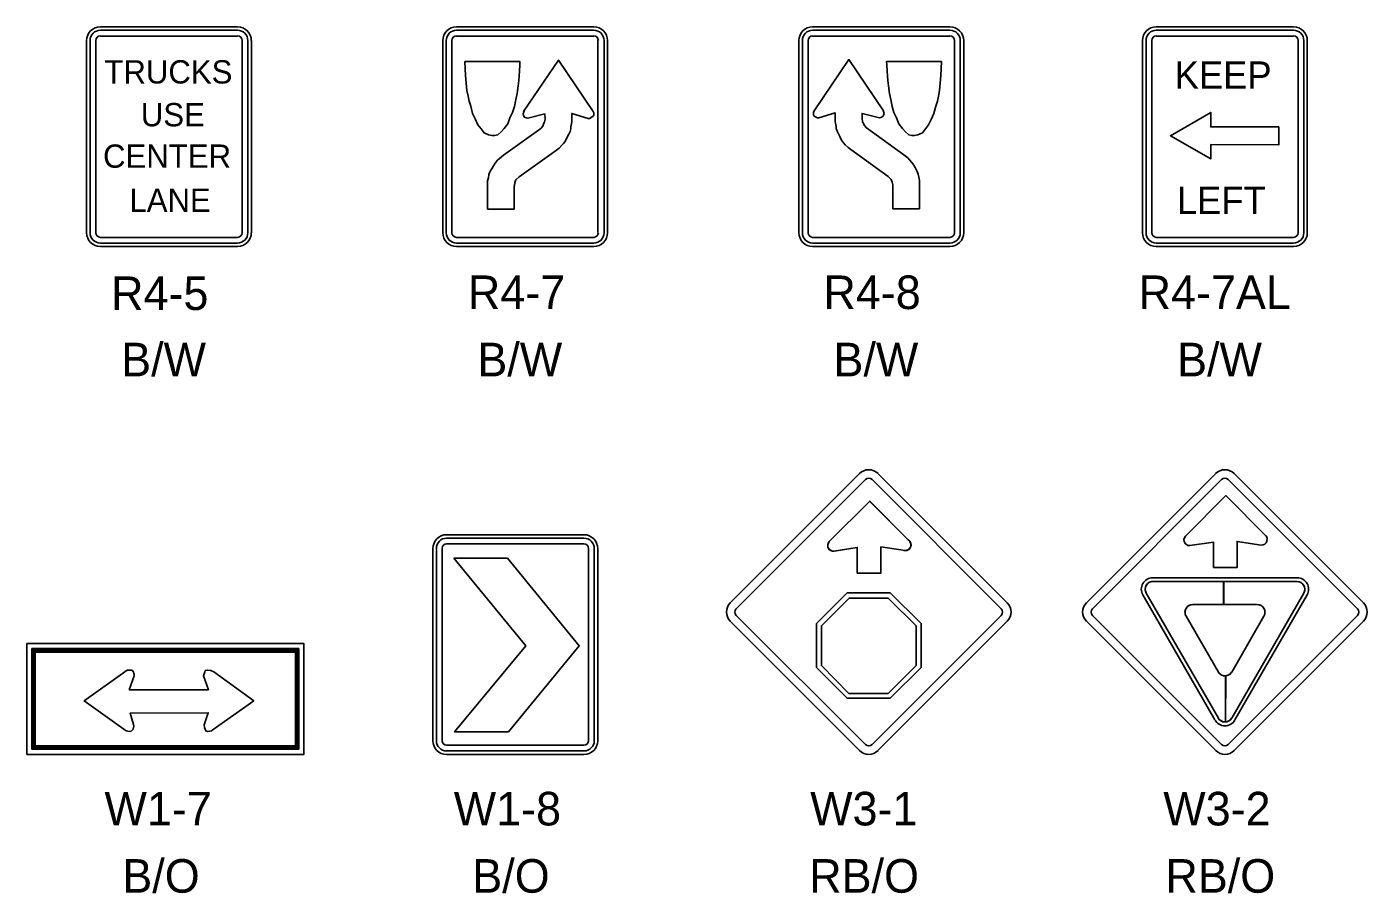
# Model space of a CAD drawing. Extents: x 10000 to 10794, y 10000 to 10499.
# Drawn here: x 10653.6 to 10793.3, y 10408.8 to 10499 of the extents above; entities that cross this region are included whole.
import ezdxf

# ---------------------------------------------------------------- set-up
doc = ezdxf.new("R2010")
doc.units = 0
doc.layers.add('DSIndex', color=7, linetype='Continuous')

msp = doc.modelspace()

# ---------------------------------------------------------------- linework, layer by layer
at = {"layer": 'DSIndex'}
for p, q in [((10661.29, 10499.04), (10675.59, 10499.04)), ((10661.29, 10498.68), (10675.59, 10498.68)), ((10698.41, 10499.04), (10712.71, 10499.04)), ((10698.41, 10498.68), (10712.71, 10498.68)), ((10749.83, 10499.04), (10735.52, 10499.04)), ((10749.83, 10498.68), (10735.52, 10498.68)), ((10771.33, 10499.04), (10785.64, 10499.04)), ((10771.33, 10498.68), (10785.64, 10498.68)), ((10659.86, 10477.58), (10659.86, 10497.61)), ((10659.86, 10477.58), (10659.86, 10497.61)), ((10660.22, 10477.58), (10660.22, 10497.61)), ((10660.81, 10477.58), (10660.81, 10497.61)), ((10661.29, 10498.08), (10675.59, 10498.08)), ((10676.07, 10477.58), (10676.07, 10497.61)), ((10676.67, 10477.58), (10676.67, 10497.61)), ((10677.03, 10477.58), (10677.03, 10497.61)), ((10696.98, 10477.58), (10696.98, 10497.61)), ((10696.98, 10477.58), (10696.98, 10497.61)), ((10697.33, 10477.58), (10697.33, 10497.61)), ((10697.93, 10477.58), (10697.93, 10497.61)), ((10698.41, 10498.08), (10712.71, 10498.08)), ((10713.15, 10477.6), (10713.15, 10497.63)), ((10713.78, 10477.58), (10713.78, 10497.61)), ((10714.14, 10477.58), (10714.14, 10497.61)), ((10734.09, 10477.58), (10734.09, 10497.61)), ((10734.09, 10477.58), (10734.09, 10497.61)), ((10734.45, 10477.58), (10734.45, 10497.61)), ((10735.05, 10477.58), (10735.05, 10497.61)), ((10749.83, 10498.08), (10735.52, 10498.08)), ((10750.3, 10477.58), (10750.3, 10497.61)), ((10750.9, 10477.58), (10750.9, 10497.61)), ((10751.26, 10477.58), (10751.26, 10497.61)), ((10769.9, 10477.58), (10769.9, 10497.61)), ((10769.9, 10477.58), (10769.9, 10497.61)), ((10770.26, 10477.58), (10770.26, 10497.61)), ((10770.86, 10477.58), (10770.86, 10497.61)), ((10771.33, 10498.08), (10785.64, 10498.08)), ((10786.12, 10477.58), (10786.12, 10497.61)), ((10786.71, 10477.58), (10786.71, 10497.61)), ((10787.07, 10477.58), (10787.07, 10497.61)), ((10661.29, 10477.1), (10675.59, 10477.1)), ((10661.29, 10476.51), (10675.59, 10476.51)), ((10698.41, 10477.1), (10712.71, 10477.1)), ((10698.41, 10476.51), (10712.71, 10476.51)), ((10749.83, 10477.1), (10735.52, 10477.1)), ((10749.83, 10476.51), (10735.52, 10476.51)), ((10771.33, 10477.1), (10785.64, 10477.1)), ((10771.33, 10476.51), (10785.64, 10476.51)), ((10661.29, 10476.15), (10675.59, 10476.15)), ((10698.41, 10476.15), (10712.71, 10476.15)), ((10749.83, 10476.15), (10735.52, 10476.15)), ((10771.33, 10476.15), (10785.64, 10476.15)), ((10726.94, 10439.02), (10740.41, 10452.49)), ((10727.56, 10438.41), (10741.02, 10451.86)), ((10741.72, 10451.86), (10755.17, 10438.41)), ((10742.33, 10452.49), (10755.8, 10439.02)), ((10764.05, 10439.02), (10777.53, 10452.49)), ((10764.68, 10438.41), (10778.14, 10451.86)), ((10778.83, 10451.86), (10792.29, 10438.41)), ((10779.44, 10452.49), (10792.92, 10439.02)), ((10741.47, 10449.62), (10737.25, 10445.41)), ((10741.46, 10449.61), (10745.62, 10445.44)), ((10697.38, 10446.12), (10711.69, 10446.12)), ((10697.38, 10445.76), (10711.69, 10445.76)), ((10695.95, 10424.66), (10695.95, 10444.69)), ((10696.31, 10424.66), (10696.31, 10444.69)), ((10696.91, 10424.66), (10696.91, 10444.69)), ((10697.38, 10445.17), (10711.69, 10445.17)), ((10712.16, 10424.66), (10712.16, 10444.69)), ((10712.76, 10424.66), (10712.76, 10444.69)), ((10713.12, 10424.66), (10713.12, 10444.69)), ((10740.16, 10444.79), (10737.76, 10444.42)), ((10740.16, 10442.13), (10740.16, 10444.79)), ((10742.64, 10442.13), (10742.64, 10444.85)), ((10742.64, 10444.85), (10745.15, 10444.46)), ((10740.16, 10442.13), (10742.64, 10442.13)), ((10770.97, 10441.64), (10786.02, 10441.64)), ((10735.92, 10436.87), (10739.12, 10440.08)), ((10739.12, 10440.08), (10743.61, 10440.08)), ((10746.82, 10436.87), (10743.61, 10440.08)), ((10777.8, 10427.01), (10770.28, 10440.04)), ((10770.97, 10441.24), (10786.02, 10441.24)), ((10786.71, 10440.04), (10779.19, 10427.01)), ((10777.45, 10426.82), (10769.93, 10439.84)), ((10775.13, 10438.84), (10781.86, 10438.84)), ((10787.05, 10439.84), (10779.53, 10426.82)), ((10741.02, 10424.25), (10727.56, 10437.71)), ((10755.17, 10437.71), (10741.72, 10424.25)), ((10778.14, 10424.25), (10764.68, 10437.71)), ((10777.8, 10431.81), (10774.44, 10437.64)), ((10792.29, 10437.71), (10778.83, 10424.25)), ((10782.55, 10437.64), (10779.19, 10431.81)), ((10740.41, 10423.63), (10726.94, 10437.1)), ((10735.92, 10432.29), (10735.92, 10436.87)), ((10735.92, 10436.87), (10735.92, 10436.87)), ((10755.8, 10437.1), (10742.33, 10423.63)), ((10746.82, 10432.3), (10746.82, 10436.87)), ((10746.82, 10436.87), (10746.82, 10436.87)), ((10777.53, 10423.63), (10764.05, 10437.1)), ((10792.92, 10437.1), (10779.44, 10423.63)), ((10705.6, 10434.56), (10705.6, 10434.56)), ((10711.17, 10434.57), (10711.17, 10434.57)), ((10654.33, 10423.93), (10654.33, 10434.08)), ((10739.13, 10429.08), (10735.92, 10432.3)), ((10743.6, 10429.08), (10746.82, 10432.3)), ((10739.07, 10429.08), (10739.11, 10429.08)), ((10743.6, 10429.08), (10739.13, 10429.08)), ((10697.38, 10424.18), (10711.69, 10424.18)), ((10697.38, 10423.59), (10711.69, 10423.59)), ((10697.38, 10423.23), (10711.69, 10423.23))]:
    msp.add_line(p, q, dxfattribs=at)
for points in [[(10699.29, 10495.44), (10705, 10495.44), (10704.99, 10495.08), (10704.96, 10494.42), (10704.89, 10493.44), (10704.82, 10492.89), (10704.72, 10492.1), (10704.58, 10491.45), (10704.44, 10490.73), (10704.25, 10490.11), (10703.98, 10489.54), (10703.74, 10488.94), (10703.36, 10488.43), (10703.08, 10488.12), (10702.7, 10487.79), (10702.38, 10487.7), (10702.1, 10487.7), (10701.74, 10487.77), (10701.28, 10487.98), (10700.97, 10488.41), (10700.63, 10488.82), (10700.37, 10489.39), (10700.08, 10490.02), (10699.89, 10490.76), (10699.72, 10491.3), (10699.61, 10491.81), (10699.49, 10492.4), (10699.42, 10493.17), (10699.36, 10493.96)], [(10701.64, 10480.04), (10701.64, 10482.42), (10701.64, 10482.66), (10701.64, 10482.99), (10701.73, 10483.32), (10701.78, 10483.65), (10701.92, 10483.99), (10702.11, 10484.32), (10702.25, 10484.56), (10702.44, 10484.84), (10702.68, 10485.13), (10702.87, 10485.32), (10703.3, 10485.66), (10707.19, 10488.46), (10707.39, 10488.69), (10707.48, 10488.88), (10707.58, 10489.12), (10707.63, 10489.4), (10707.62, 10489.97), (10705.84, 10489.51), (10705.68, 10489.55), (10705.49, 10489.64), (10705.39, 10489.79), (10705.34, 10489.97), (10705.44, 10490.26), (10705.4, 10490.22), (10709.02, 10495.57), (10712.64, 10490.22), (10712.71, 10490.07), (10712.71, 10489.83), (10712.61, 10489.69), (10712.42, 10489.59), (10712.33, 10489.5), (10712.14, 10489.5), (10710.42, 10490.01), (10710.42, 10489.4), (10710.43, 10489.12), (10710.33, 10488.6), (10710.33, 10488.41), (10710.24, 10488.12), (10710.1, 10487.84), (10709.95, 10487.55), (10709.76, 10487.17), (10709.57, 10486.89), (10709.38, 10486.7), (10709.1, 10486.41), (10708.81, 10486.2), (10704.93, 10483.4), (10704.58, 10483.08), (10704.49, 10482.8), (10704.44, 10482.51), (10704.43, 10482.42), (10704.43, 10480.04)], [(10746.66, 10480.09), (10746.66, 10482.47), (10746.67, 10482.71), (10746.67, 10483.04), (10746.57, 10483.37), (10746.53, 10483.7), (10746.38, 10484.04), (10746.19, 10484.37), (10746.05, 10484.61), (10745.86, 10484.89), (10745.62, 10485.18), (10745.43, 10485.37), (10745.01, 10485.71), (10741.12, 10488.51), (10740.92, 10488.74), (10740.82, 10488.93), (10740.73, 10489.17), (10740.67, 10489.45), (10740.68, 10490.02), (10742.47, 10489.56), (10742.63, 10489.6), (10742.82, 10489.69), (10742.91, 10489.83), (10742.96, 10490.02), (10742.87, 10490.31), (10742.9, 10490.27), (10739.28, 10495.62), (10735.67, 10490.27), (10735.6, 10490.12), (10735.6, 10489.88), (10735.69, 10489.74), (10735.88, 10489.64), (10735.98, 10489.55), (10736.17, 10489.55), (10737.88, 10490.06), (10737.88, 10489.45), (10737.88, 10489.17), (10737.97, 10488.65), (10737.97, 10488.46), (10738.07, 10488.17), (10738.21, 10487.89), (10738.35, 10487.6), (10738.54, 10487.22), (10738.73, 10486.94), (10738.92, 10486.75), (10739.21, 10486.46), (10739.49, 10486.25), (10743.38, 10483.45), (10743.72, 10483.13), (10743.82, 10482.85), (10743.86, 10482.56), (10743.88, 10482.47), (10743.88, 10480.09)], [(10748.94, 10495.44), (10743.23, 10495.44), (10743.25, 10495.08), (10743.28, 10494.42), (10743.35, 10493.44), (10743.42, 10492.89), (10743.52, 10492.1), (10743.66, 10491.45), (10743.79, 10490.73), (10743.98, 10490.11), (10744.26, 10489.54), (10744.5, 10488.94), (10744.88, 10488.43), (10745.15, 10488.12), (10745.53, 10487.79), (10745.86, 10487.7), (10746.13, 10487.7), (10746.49, 10487.77), (10746.96, 10487.98), (10747.27, 10488.41), (10747.61, 10488.82), (10747.87, 10489.39), (10748.16, 10490.02), (10748.35, 10490.76), (10748.52, 10491.3), (10748.62, 10491.81), (10748.74, 10492.4), (10748.81, 10493.17), (10748.88, 10493.96)], [(10784.11, 10488.63), (10784.11, 10486.75), (10777.01, 10486.77), (10777.01, 10485.27), (10772.81, 10487.69), (10777.01, 10490.11), (10777.01, 10488.61)], [(10777.28, 10442.7), (10779.75, 10442.7), (10779.75, 10445.42), (10782.26, 10445.04), (10782.47, 10445.07), (10782.66, 10445.15), (10782.78, 10445.29), (10782.86, 10445.46), (10782.87, 10445.75), (10782.78, 10445.99), (10782.74, 10446.02), (10778.58, 10450.2), (10774.37, 10445.98), (10774.21, 10445.67), (10774.23, 10445.41), (10774.36, 10445.17), (10774.61, 10445.01), (10774.84, 10444.98), (10777.28, 10445.36)], [(10740.16, 10442.13), (10742.64, 10442.13), (10742.64, 10444.85), (10745.15, 10444.46), (10745.35, 10444.49), (10745.55, 10444.58), (10745.66, 10444.72), (10745.75, 10444.89), (10745.76, 10445.17), (10745.66, 10445.41), (10745.62, 10445.44), (10741.47, 10449.62), (10737.25, 10445.41), (10737.1, 10445.1), (10737.12, 10444.83), (10737.24, 10444.6), (10737.5, 10444.44), (10737.72, 10444.41), (10740.16, 10444.79)], [(10698.13, 10443.69), (10703.72, 10443.69), (10711.19, 10434.55), (10703.81, 10425.57), (10698.2, 10425.57), (10705.62, 10434.54)], [(10778.35, 10441.24), (10778.35, 10438.84), (10775.13, 10438.84), (10774.98, 10438.83), (10774.88, 10438.8), (10774.78, 10438.75), (10774.69, 10438.7), (10774.62, 10438.66), (10774.57, 10438.61), (10774.5, 10438.53), (10774.45, 10438.47), (10774.4, 10438.38), (10774.36, 10438.28), (10774.34, 10438.19), (10774.32, 10438.1), (10774.33, 10438), (10774.34, 10437.86), (10774.38, 10437.74), (10774.44, 10437.64), (10777.8, 10431.81), (10777.86, 10431.71), (10777.94, 10431.64), (10778.02, 10431.58), (10778.1, 10431.53), (10778.17, 10431.48), (10778.25, 10431.45), (10778.35, 10431.43), (10778.42, 10431.42), (10778.49, 10431.42), (10778.55, 10431.42), (10778.54, 10426.62), (10778.4, 10426.62), (10778.3, 10426.63), (10778.23, 10426.65), (10778.13, 10426.68), (10778.06, 10426.75), (10778, 10426.79), (10777.94, 10426.82), (10777.9, 10426.88), (10777.86, 10426.93), (10777.8, 10427.01), (10770.28, 10440.04), (10770.27, 10440.08), (10770.23, 10440.17), (10770.2, 10440.27), (10770.18, 10440.34), (10770.18, 10440.43), (10770.2, 10440.57), (10770.2, 10440.66), (10770.24, 10440.75), (10770.29, 10440.85), (10770.28, 10440.84), (10770.34, 10440.94), (10770.43, 10441.03), (10770.52, 10441.11), (10770.62, 10441.16), (10770.74, 10441.21), (10770.84, 10441.24), (10770.97, 10441.24)], [(10778.38, 10441.24), (10778.38, 10438.84), (10781.86, 10438.84), (10782.05, 10438.82), (10782.2, 10438.77), (10782.28, 10438.72), (10782.4, 10438.63), (10782.52, 10438.49), (10782.6, 10438.35), (10782.65, 10438.19), (10782.66, 10438.02), (10782.65, 10437.88), (10782.6, 10437.73), (10782.55, 10437.64), (10779.19, 10431.81), (10779.1, 10431.7), (10779.03, 10431.6), (10778.92, 10431.54), (10778.81, 10431.47), (10778.69, 10431.44), (10778.57, 10431.42), (10778.54, 10426.62), (10778.66, 10426.62), (10778.75, 10426.66), (10778.83, 10426.69), (10778.9, 10426.74), (10778.96, 10426.77), (10779.03, 10426.82), (10779.09, 10426.88), (10779.15, 10426.95), (10779.19, 10427.01), (10779.19, 10427.01), (10786.71, 10440.04), (10786.74, 10440.1), (10786.79, 10440.22), (10786.8, 10440.32), (10786.82, 10440.42), (10786.82, 10440.52), (10786.79, 10440.64), (10786.77, 10440.72), (10786.74, 10440.79), (10786.7, 10440.87), (10786.64, 10440.95), (10786.57, 10441.01), (10786.51, 10441.07), (10786.43, 10441.13), (10786.33, 10441.18), (10786.24, 10441.21), (10786.15, 10441.22), (10786.02, 10441.24)], [(10739.3, 10429.57), (10743.39, 10429.57), (10746.3, 10432.48), (10746.3, 10436.62), (10743.4, 10439.52), (10739.34, 10439.52), (10736.44, 10436.61), (10736.44, 10432.48)], [(10664.3, 10429.95), (10664.82, 10431.41), (10664.81, 10431.56), (10664.71, 10431.89), (10664.54, 10432.02), (10664.34, 10432.02), (10664.07, 10432.01), (10659.6, 10428.81), (10663.97, 10425.69), (10664.17, 10425.65), (10664.37, 10425.61), (10664.51, 10425.66), (10664.7, 10425.87), (10664.78, 10426.18), (10664.75, 10426.36), (10664.39, 10427.52), (10672.53, 10427.57), (10672.11, 10426.31), (10672.16, 10426.02), (10672.28, 10425.68), (10672.45, 10425.63), (10672.89, 10425.68), (10673.06, 10425.82), (10677.27, 10428.81), (10673.11, 10431.85), (10672.79, 10431.99), (10672.45, 10432.01), (10672.23, 10431.97), (10672.18, 10431.82), (10672.04, 10431.43), (10672.56, 10429.96)]]:
    msp.add_lwpolyline(points, close=True, dxfattribs=at)
for points in [[(10653.63, 10434.78), (10682.5, 10434.78), (10682.5, 10423.23), (10653.63, 10423.23), (10653.63, 10434.78)], [(10654.16, 10434.25), (10681.97, 10434.25), (10681.97, 10423.76), (10654.16, 10423.76), (10654.16, 10434.25)], [(10654.22, 10434.19), (10681.91, 10434.19), (10681.91, 10423.82), (10654.22, 10423.82), (10654.22, 10434.19)], [(10654.27, 10434.13), (10681.85, 10434.13), (10681.85, 10423.88), (10654.27, 10423.88), (10654.27, 10434.13)], [(10654.33, 10434.08), (10681.8, 10434.08), (10681.8, 10423.93), (10654.33, 10423.93)], [(10654.39, 10434.02), (10681.74, 10434.02)], [(10654.39, 10434.02), (10681.74, 10434.02), (10681.74, 10423.99), (10654.39, 10423.99), (10654.39, 10434.02)], [(10654.45, 10433.96), (10681.68, 10433.96), (10681.68, 10424.05), (10654.45, 10424.05), (10654.45, 10433.96)], [(10654.5, 10433.9), (10681.62, 10433.9), (10681.62, 10424.11), (10654.5, 10424.11), (10654.5, 10433.9)]]:
    msp.add_lwpolyline(points, dxfattribs=at)
for centre, radius, start, end in [((10661.29, 10497.61), 1.43, 90, 180), ((10661.29, 10497.61), 1.07, 90, 180), ((10675.59, 10497.61), 1.43, 0, 90), ((10675.59, 10497.61), 1.07, 0, 90), ((10698.41, 10497.61), 1.43, 90, 180), ((10698.41, 10497.61), 1.07, 90, 180), ((10712.71, 10497.61), 1.43, 0, 90), ((10712.71, 10497.61), 1.07, 0, 90), ((10735.52, 10497.61), 1.43, 90, 180), ((10735.52, 10497.61), 1.07, 90, 180), ((10749.83, 10497.61), 1.43, 0, 90), ((10749.83, 10497.61), 1.07, 0, 90), ((10771.33, 10497.61), 1.43, 90, 180), ((10771.33, 10497.61), 1.07, 90, 180), ((10785.64, 10497.61), 1.43, 0, 90), ((10785.64, 10497.61), 1.07, 0, 90), ((10661.29, 10497.61), 0.477, 90, 180), ((10675.59, 10497.61), 0.477, 0, 90), ((10698.41, 10497.61), 0.477, 90, 180), ((10712.71, 10497.61), 0.477, 0, 90), ((10735.52, 10497.61), 0.477, 90, 180), ((10749.83, 10497.61), 0.477, 0, 90), ((10771.33, 10497.61), 0.477, 90, 180), ((10785.64, 10497.61), 0.477, 0, 90), ((10661.29, 10477.58), 1.43, 180, 270), ((10661.29, 10477.58), 1.07, 180, 270), ((10661.29, 10477.58), 0.477, 180, 270), ((10675.59, 10477.58), 1.43, 270, 0), ((10675.59, 10477.58), 1.07, 270, 0), ((10675.59, 10477.58), 0.477, 270, 0), ((10698.41, 10477.58), 1.43, 180, 270), ((10698.41, 10477.58), 1.07, 180, 270), ((10698.41, 10477.58), 0.477, 180, 270), ((10712.71, 10477.58), 1.43, 270, 0), ((10712.71, 10477.58), 1.07, 270, 0), ((10712.71, 10477.58), 0.477, 270, 0), ((10735.52, 10477.58), 1.43, 180, 270), ((10735.52, 10477.58), 1.07, 180, 270), ((10735.52, 10477.58), 0.477, 180, 270), ((10749.83, 10477.58), 1.43, 270, 0), ((10749.83, 10477.58), 1.07, 270, 0), ((10749.83, 10477.58), 0.477, 270, 0), ((10771.33, 10477.58), 1.43, 180, 270), ((10771.33, 10477.58), 1.07, 180, 270), ((10771.33, 10477.58), 0.477, 180, 270), ((10785.64, 10477.58), 1.43, 270, 0), ((10785.64, 10477.58), 1.07, 270, 0), ((10785.64, 10477.58), 0.477, 270, 0), ((10741.37, 10451.53), 1.36, 45, 135), ((10778.48, 10451.53), 1.36, 45, 135), ((10741.37, 10451.52), 0.49, 45, 135), ((10778.48, 10451.52), 0.49, 45, 135), ((10697.38, 10444.69), 1.43, 90, 180), ((10697.38, 10444.69), 1.07, 90, 180), ((10711.69, 10444.69), 1.43, 0, 90), ((10711.69, 10444.69), 1.07, 0, 90), ((10697.38, 10444.69), 0.477, 90, 180), ((10711.69, 10444.69), 0.477, 0, 90), ((10737.68, 10445), 0.591, 135.3904, 277.6306), ((10745.18, 10445.06), 0.591, 255.3843, 60.3263), ((10770.97, 10440.44), 1.2, 90, 210), ((10786.01, 10440.44), 1.2, 330, 90), ((10770.97, 10440.44), 0.8, 90, 210), ((10786.01, 10440.44), 0.8, 330, 90), ((10727.9, 10438.06), 1.36, 135, 225), ((10754.84, 10438.06), 1.36, 315, 45), ((10765.01, 10438.06), 1.36, 135, 225), ((10775.13, 10438.04), 0.8, 90, 210), ((10781.86, 10438.04), 0.8, 330, 90), ((10791.95, 10438.06), 1.36, 315, 45), ((10727.91, 10438.06), 0.49, 135, 225), ((10754.83, 10438.06), 0.49, 315, 45), ((10765.02, 10438.06), 0.49, 135, 225), ((10791.94, 10438.06), 0.49, 315, 45), ((10778.49, 10432.21), 0.8, 210, 330), ((10778.49, 10427.41), 1.2, 210, 330), ((10778.49, 10427.41), 0.8, 210, 330), ((10697.38, 10424.66), 1.43, 180, 270), ((10697.38, 10424.66), 1.07, 180, 270), ((10697.38, 10424.66), 0.477, 180, 270), ((10711.69, 10424.66), 1.43, 270, 0), ((10711.69, 10424.66), 1.07, 270, 0), ((10711.69, 10424.66), 0.477, 270, 0), ((10741.37, 10424.59), 1.36, 225, 315), ((10741.37, 10424.6), 0.49, 225, 315), ((10778.49, 10424.59), 1.36, 225, 315), ((10778.48, 10424.6), 0.49, 225, 315)]:
    msp.add_arc(centre, radius, start, end, dxfattribs=at)

# ---------------------------------------------------------------- texts
for s, height, p in [('TRUCKS', 2.427, (10661.71, 10493.13)), ('KEEP', 2.831, (10773.25, 10492.6)), ('USE', 2.425, (10665.51, 10488.67)), ('CENTER', 2.427, (10661.57, 10484.35)), ('LANE', 2.427, (10664.32, 10479.76)), ('LEFT', 2.831, (10773.48, 10479.54)), ('R4-5', 3.5, (10662.41, 10469.53)), ('R4-7', 3.5, (10699.59, 10469.63)), ('R4-8', 3.5, (10736.64, 10469.63)), ('R4-7AL', 3.5, (10769.49, 10469.63)), ('B/W', 3.5, (10663.46, 10462.62)), ('B/W', 3.5, (10700.58, 10462.62)), ('B/W', 3.5, (10737.69, 10462.62)), ('B/W', 3.5, (10773.5, 10462.62)), ('W1-7', 3.5, (10661.72, 10415.83)), ('W1-8', 3.5, (10698.12, 10415.83)), ('W3-1', 3.5, (10735.26, 10415.83)), ('W3-2', 3.5, (10772.06, 10415.83)), ('B/O', 3.5, (10663.58, 10408.82)), ('B/O', 3.5, (10700.05, 10408.82)), ('RB/O', 3.5, (10735.16, 10408.82)), ('RB/O', 3.5, (10772.28, 10408.82))]:
    msp.add_text(s, height=height, dxfattribs=at).set_placement(p)

doc.saveas('drawing.dxf')
